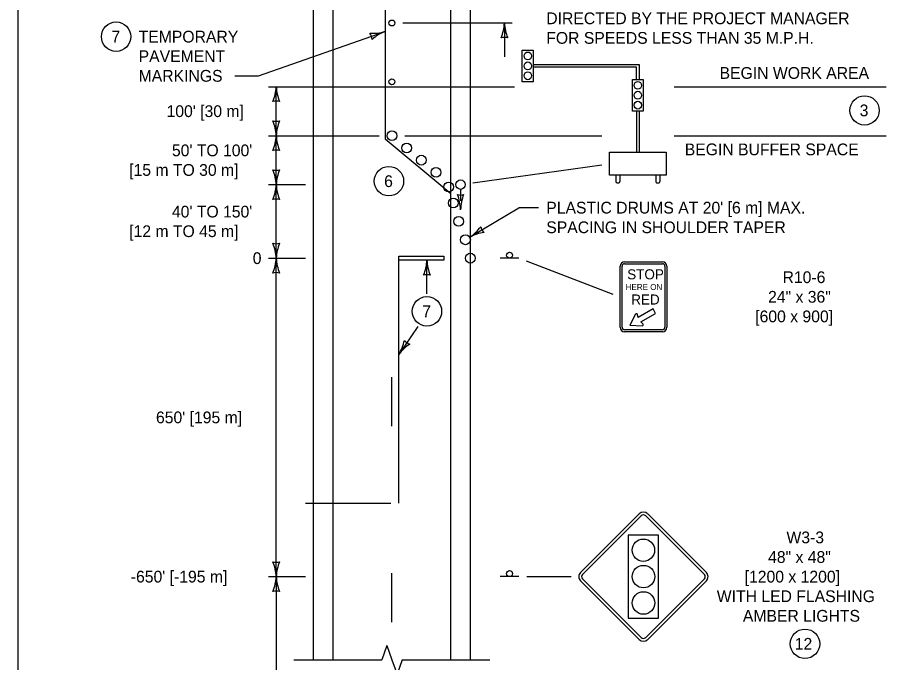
# Model space of a CAD drawing. Extents: x 49991.4 to 50021, y 49987.6 to 50011.4.
# Drawn here: x 50000.336 to 50004.847, y 50004.934 to 50008.223 of the extents above; entities that cross this region are included whole.
import ezdxf

# ---------------------------------------------------------------- set-up
doc = ezdxf.new("R2010")
doc.units = 0
for name, color, linetype in [('Level 1', 7, 'Continuous'), ('Level 2', 7, 'Continuous'), ('Level 3', 7, 'Continuous'), ('Level 6', 7, 'Continuous')]:
    doc.layers.add(name, color=color, linetype=linetype)

msp = doc.modelspace()

# ---------------------------------------------------------------- linework, layer by layer
at = {"layer": 'Level 1'}
for p, q in [((50001.8443, 50004.9471), (50001.8443, 50010.921)), ((50001.9443, 50004.9471), (50001.9443, 50010.921)), ((50002.5443, 50004.9471), (50002.5443, 50010.921)), ((50002.6443, 50004.9471), (50002.6443, 50010.921)), ((50002.2093, 50008.9873), (50002.2093, 50007.6045)), ((50002.9651, 50007.984), (50003.5048, 50007.984)), ((50003.5048, 50007.984), (50003.5048, 50007.908)), ((50003.4921, 50007.9701), (50002.9651, 50007.9701)), ((50003.4921, 50007.908), (50003.4921, 50007.9701)), ((50003.4921, 50007.7462), (50003.4921, 50007.5369)), ((50003.5048, 50007.7462), (50003.5048, 50007.5369)), ((50002.2093, 50007.6045), (50002.5443, 50007.3253)), ((50003.3859, 50007.4192), (50003.3859, 50007.3873)), ((50003.4071, 50007.4192), (50003.4071, 50007.3873)), ((50003.5898, 50007.4192), (50003.5898, 50007.3873)), ((50003.611, 50007.4192), (50003.611, 50007.3873)), ((50002.5943, 50007.3469), (50002.5943, 50007.2885)), ((50003.3923, 50007.3803), (50003.4008, 50007.3803)), ((50003.5962, 50007.3803), (50003.6047, 50007.3803)), ((50002.2793, 50005.7459), (50002.2793, 50006.9859)), ((50002.8923, 50006.9959), (50002.7963, 50006.9959)), ((50003.4086, 50006.643), (50003.4086, 50006.9545)), ((50003.4179, 50006.643), (50003.4179, 50006.9545)), ((50003.4309, 50006.9767), (50003.6237, 50006.9767)), ((50003.4309, 50006.9675), (50003.6237, 50006.9675)), ((50003.6367, 50006.9545), (50003.6367, 50006.643)), ((50003.646, 50006.9545), (50003.646, 50006.643)), ((50003.5761, 50006.7367), (50003.5001, 50006.6928)), ((50003.5891, 50006.7142), (50003.5761, 50006.7367)), ((50003.4871, 50006.7097), (50003.4574, 50006.6532)), ((50003.5001, 50006.6928), (50003.4967, 50006.7084)), ((50003.5131, 50006.6704), (50003.5891, 50006.7142)), ((50003.5249, 50006.6596), (50003.5131, 50006.6704)), ((50003.6237, 50006.63), (50003.4309, 50006.63)), ((50003.4574, 50006.6532), (50003.5212, 50006.6507)), ((50003.4086, 50006.6207), (50003.4086, 50006.6207)), ((50003.6237, 50006.6207), (50003.4309, 50006.6207)), ((50002.2443, 50006.1388), (50002.2443, 50006.3888)), ((50003.5058, 50005.6916), (50003.2064, 50005.3922)), ((50003.5058, 50005.6916), (50003.2064, 50005.3922)), ((50003.5159, 50005.6815), (50003.2165, 50005.3821)), ((50003.5159, 50005.6815), (50003.2165, 50005.3821)), ((50003.5159, 50005.6815), (50003.5159, 50005.6815)), ((50003.5159, 50005.6815), (50003.5159, 50005.6815)), ((50003.8379, 50005.3821), (50003.5385, 50005.6815)), ((50003.8379, 50005.3821), (50003.5385, 50005.6815)), ((50003.848, 50005.3922), (50003.5486, 50005.6916)), ((50003.848, 50005.3922), (50003.5486, 50005.6916)), ((50002.2443, 50005.1388), (50002.2443, 50005.3888)), ((50002.8923, 50005.3709), (50002.7963, 50005.3709)), ((50003.2064, 50005.3495), (50003.5058, 50005.0501)), ((50003.2064, 50005.3495), (50003.5058, 50005.0501)), ((50003.2165, 50005.3596), (50003.5159, 50005.0602)), ((50003.2165, 50005.3596), (50003.5159, 50005.0602)), ((50003.5385, 50005.0602), (50003.8379, 50005.3596)), ((50003.5385, 50005.0602), (50003.8379, 50005.3596)), ((50003.5486, 50005.0501), (50003.848, 50005.3495)), ((50003.5486, 50005.0501), (50003.848, 50005.3495)), ((50003.5272, 50005.0287), (50003.5272, 50005.0287)), ((50003.5272, 50005.0287), (50003.5272, 50005.0287))]:
    msp.add_line(p, q, dxfattribs=at)
for points in [[(50008.6146, 50011.2628), (50000.3356, 50011.2628), (50000.3356, 50000.0624), (50008.6146, 50000.0624)], [(50002.9093, 50008.0579), (50002.9651, 50008.0579), (50002.9651, 50007.8961), (50002.9093, 50007.8961)], [(50003.4704, 50007.908), (50003.5261, 50007.908), (50003.5261, 50007.7462), (50003.4704, 50007.7462)], [(50003.354, 50007.5369), (50003.6429, 50007.5369), (50003.6429, 50007.4192), (50003.354, 50007.4192)], [(50002.2793, 50007.0059), (50002.5093, 50007.0059), (50002.5093, 50006.9859), (50002.2793, 50006.9859)], [(50003.6045, 50005.1592), (50003.6045, 50005.5825), (50003.4499, 50005.5825), (50003.4499, 50005.1592)], [(50003.6045, 50005.1592), (50003.6045, 50005.5825), (50003.4499, 50005.5825), (50003.4499, 50005.1592)]]:
    msp.add_lwpolyline(points, close=True, dxfattribs=at)
msp.add_lwpolyline([(50003.6045, 50005.1593), (50003.6043, 50005.1592)], dxfattribs=at)
msp.add_lwpolyline([(50003.6045, 50005.1593), (50003.6043, 50005.1592)], dxfattribs=at)
for centre, radius in [((50002.2443, 50008.1958), 0.015), ((50002.2443, 50007.8958), 0.015), ((50002.2443, 50007.6209), 0.025), ((50002.3193, 50007.5584), 0.025), ((50002.3943, 50007.4959), 0.025), ((50002.4693, 50007.4334), 0.025), ((50002.5943, 50007.3709), 0.024), ((50002.5337, 50007.3594), 0.025), ((50002.5576, 50007.2771), 0.025), ((50002.5844, 50007.1834), 0.025), ((50002.6193, 50007.0896), 0.025), ((50002.6443, 50006.9959), 0.025), ((50002.8443, 50007.0111), 0.0152), ((50003.5266, 50005.5055), 0.0572), ((50003.5266, 50005.5055), 0.0572), ((50003.5269, 50005.3709), 0.0575), ((50003.5269, 50005.3709), 0.0575), ((50002.8443, 50005.3861), 0.0152), ((50003.5269, 50005.2364), 0.0575), ((50003.5269, 50005.2364), 0.0575)]:
    msp.add_circle(centre, radius, dxfattribs=at)
for centre, radius, start, end in [((50003.4309, 50006.9545), 0.0223, 90, 180), ((50003.4309, 50006.9545), 0.013, 90, 180), ((50003.6237, 50006.9545), 0.0223, 360, 90), ((50003.6237, 50006.9545), 0.013, 360, 90), ((50003.4917, 50006.7073), 0.00514, 12.3804, 152.2438), ((50003.4309, 50006.643), 0.0223, 180, 270), ((50003.4309, 50006.643), 0.013, 180, 270), ((50003.5214, 50006.6558), 0.00514, 267.757, 47.6186), ((50003.6237, 50006.643), 0.0223, 270, 360), ((50003.6237, 50006.643), 0.013, 270, 360), ((50003.5272, 50005.6702), 0.0302, 45.0001, 134.9999), ((50003.5272, 50005.6702), 0.0302, 45.0001, 134.9999), ((50003.5272, 50005.6702), 0.016, 45.0001, 134.9999), ((50003.5272, 50005.6702), 0.016, 45.0001, 134.9999), ((50003.2278, 50005.3709), 0.0302, 134.9999, 225.0001), ((50003.2278, 50005.3709), 0.0302, 134.9999, 225.0001), ((50003.2278, 50005.3709), 0.016, 134.9999, 225.0001), ((50003.2278, 50005.3709), 0.016, 134.9999, 225.0001), ((50003.8266, 50005.3709), 0.016, 314.9999, 45.0001), ((50003.8266, 50005.3709), 0.016, 314.9999, 45.0001), ((50003.8266, 50005.3709), 0.0302, 314.9999, 45.0001), ((50003.8266, 50005.3709), 0.0302, 314.9999, 45.0001), ((50003.5272, 50005.0715), 0.0302, 225.0001, 314.9999), ((50003.5272, 50005.0715), 0.0302, 225.0001, 314.9999), ((50003.5272, 50005.0715), 0.016, 225.0001, 314.9999), ((50003.5272, 50005.0715), 0.016, 225.0001, 314.9999)]:
    msp.add_arc(centre, radius, start, end, dxfattribs=at)
for centre in [(50002.9372, 50008.0276), (50002.9372, 50007.977), (50002.9372, 50007.9265), (50003.4982, 50007.8777), (50003.4982, 50007.8271), (50003.4982, 50007.7765)]:
    msp.add_ellipse(centre, major_axis=(0, 0.0202), ratio=0.91873, dxfattribs=at)
for centre, major_axis, ratio, start_param, end_param in [((50003.3923, 50007.3873), (0, -0.00694), 0.91873, 4.712389, 6.283185), ((50003.4008, 50007.3873), (0, 0.00694), 0.91873, 3.141779, 4.712402), ((50003.5962, 50007.3873), (0, 0.00693), 0.91873, 1.570718, 3.142197), ((50003.6047, 50007.3873), (0, 0.00693), 0.91873, 3.14129, 4.712467), ((50002.5943, 50007.3738), (0, -0.0558), 0.908162, 5.971449, 6.594922), ((50002.3792, 50007.2316), (0, 0.2372), 0.908162, 4.761735, 5.097708), ((50002.7997, 50007.234), (0, -0.2263), 0.908162, 4.318922, 4.671191)]:
    msp.add_ellipse(centre, major_axis=major_axis, ratio=ratio, start_param=start_param, end_param=end_param, dxfattribs=at)
at = {"layer": 'Level 2'}
for centre in [(50000.8375, 50008.1262), (50004.6549, 50007.7497), (50002.229, 50007.3887), (50002.4229, 50006.7247), (50004.3509, 50005.0281)]:
    msp.add_circle(centre, 0.075, dxfattribs=at)
at = {"layer": 'Level 3'}
for p, q in [((50002.2993, 50008.1958), (50002.8578, 50008.1958)), ((50002.8178, 50008.1958), (50002.8178, 50008.0224)), ((50001.6143, 50007.8709), (50001.8043, 50007.8709)), ((50001.6543, 50007.6209), (50001.6543, 50007.8709)), ((50001.8043, 50007.8709), (50002.8693, 50007.8709)), ((50003.6829, 50007.8709), (50004.7645, 50007.8709)), ((50001.6143, 50007.6209), (50002.1793, 50007.6209)), ((50001.6543, 50007.3709), (50001.6543, 50007.6209)), ((50002.3093, 50007.6209), (50003.314, 50007.6209)), ((50003.6829, 50007.6209), (50004.7645, 50007.6209)), ((50002.6577, 50007.3798), (50003.3144, 50007.4724)), ((50001.6143, 50007.3709), (50001.8043, 50007.3709)), ((50001.6543, 50006.9959), (50001.6543, 50007.3709)), ((50002.6407, 50007.1025), (50002.8919, 50007.2535)), ((50002.9914, 50007.2535), (50002.8919, 50007.2535)), ((50001.6143, 50006.9959), (50001.8043, 50006.9959)), ((50001.6543, 50005.7459), (50001.6543, 50006.9959)), ((50002.4229, 50006.8147), (50002.4229, 50006.9881)), ((50002.9297, 50006.9816), (50003.3713, 50006.813)), ((50002.3763, 50006.6477), (50002.2791, 50006.5041)), ((50001.6543, 50005.3709), (50001.6543, 50005.7459)), ((50001.8043, 50005.7459), (50002.2393, 50005.7459)), ((50001.6143, 50005.3709), (50001.8043, 50005.3709)), ((50001.6543, 50005.3709), (50001.6544, 50004.8435)), ((50002.9323, 50005.3709), (50003.1576, 50005.3709))]:
    msp.add_line(p, q, dxfattribs=at)
msp.add_lwpolyline([(50001.4427, 50007.9262), (50001.5644, 50007.9262), (50002.2093, 50008.1528)], dxfattribs=at)
for centre, radius, start, end in [((50002.5957, 50008.2049), 0.2223, 337.456, 357.6395), ((50003.0505, 50008.2073), 0.233, 182.8273, 202.0772), ((50002.1443, 50008.3654), 0.2223, 266.8124, 286.9959), ((50002.0883, 50008.1103), 0.0548, 1.4952, 37.2175), ((50002.2973, 50007.937), 0.233, 112.1837, 131.4335), ((50002.8178, 50008.0676), 0.0548, 72.1388, 107.8612), ((50001.4322, 50007.88), 0.2223, 337.456, 357.6395), ((50001.887, 50007.8823), 0.233, 182.8273, 202.0772), ((50001.6543, 50007.7426), 0.0548, 72.1388, 107.8612), ((50001.6543, 50007.7491), 0.0548, 252.1388, 287.8612), ((50001.4216, 50007.6094), 0.233, 2.8273, 22.0772), ((50001.8764, 50007.6117), 0.2223, 157.456, 177.6395), ((50001.4322, 50007.63), 0.2223, 337.456, 357.6395), ((50001.887, 50007.6323), 0.233, 182.8273, 202.0772), ((50001.6543, 50007.4926), 0.0548, 72.1388, 107.8612), ((50001.6543, 50007.4991), 0.0548, 252.1388, 287.8612), ((50001.4216, 50007.3594), 0.233, 2.8273, 22.0772), ((50001.8764, 50007.3617), 0.2223, 157.456, 177.6395), ((50001.4322, 50007.38), 0.2223, 337.456, 357.6395), ((50001.887, 50007.3823), 0.233, 182.8273, 202.0772), ((50001.6543, 50007.2426), 0.0548, 72.1388, 107.8612), ((50002.511, 50007.296), 0.233, 303.8392, 323.0891), ((50002.7473, 50006.9074), 0.2223, 98.4679, 118.6514), ((50002.7506, 50007.1685), 0.0548, 193.1507, 228.8731), ((50001.6543, 50007.1241), 0.0548, 252.1388, 287.8612), ((50001.4216, 50006.9844), 0.233, 2.8273, 22.0772), ((50001.8764, 50006.9867), 0.2223, 157.456, 177.6395), ((50001.4322, 50007.005), 0.2223, 337.456, 357.6395), ((50001.887, 50007.0073), 0.233, 182.8273, 202.0772), ((50001.6543, 50006.8676), 0.0548, 72.1388, 107.8612), ((50002.0799, 50006.625), 0.233, 328.7394, 347.9892), ((50002.4579, 50006.372), 0.2223, 123.3681, 143.5516), ((50002.351, 50006.6102), 0.0548, 218.0509, 253.7732), ((50001.6543, 50005.4991), 0.0548, 252.1388, 287.8612), ((50001.4216, 50005.3594), 0.233, 2.8273, 22.0772), ((50001.8764, 50005.3617), 0.2223, 157.456, 177.6395), ((50001.4322, 50005.38), 0.2223, 337.456, 357.6395), ((50001.887, 50005.3823), 0.233, 182.8273, 202.0772), ((50001.6543, 50005.2426), 0.0548, 72.1388, 107.8612)]:
    msp.add_arc(centre, radius, start, end, dxfattribs=at)
for centre, major_axis, start_param, end_param in [((50002.2008, 50006.9953), (0, -0.226), 1.177329, 1.529598), ((50002.6557, 50006.9976), (0, -0.2369), 4.761735, 5.097708), ((50002.4229, 50006.8556), (0, 0.0557), 5.971449, 6.594922)]:
    msp.add_ellipse(centre, major_axis=major_axis, ratio=0.983712, start_param=start_param, end_param=end_param, dxfattribs=at)
at = {"layer": 'Level 6'}
for p, q in [((50002.2184, 50005.0202), (50002.1925, 50004.9471)), ((50002.2184, 50005.0202), (50002.2443, 50004.9471)), ((50001.7443, 50004.9471), (50002.1925, 50004.9471)), ((50002.2443, 50004.9471), (50002.2702, 50004.874)), ((50002.2961, 50004.9471), (50002.2702, 50004.874)), ((50002.2961, 50004.9471), (50002.7443, 50004.9471))]:
    msp.add_line(p, q, dxfattribs=at)

# ---------------------------------------------------------------- texts
at = {"layer": 'Level 1'}
for s, height, p in [('STOP', 0.0514, (50003.4442, 50006.8877)), ('HERE ON', 0.03063, (50003.4363, 50006.8333)), ('RED', 0.0514, (50003.4648, 50006.7591))]:
    msp.add_text(s, height=height, rotation=360, dxfattribs=at).set_placement(p)
at = {"layer": 'Level 2'}
for s, p in [('DIRECTED BY THE PROJECT MANAGER ', (50003.0314, 50008.1897)), ('7', (50000.8137, 50008.0962)), ('TEMPORARY', (50000.9525, 50008.0962)), ('FOR SPEEDS LESS THAN 35 M.P.H.', (50003.0314, 50008.0897)), ('PAVEMENT', (50000.9525, 50007.9962)), ('MARKINGS', (50000.9525, 50007.8962)), ('BEGIN WORK AREA', (50003.9153, 50007.9109)), ("100' [30 m]", (50001.0948, 50007.7159)), ('3', (50004.6297, 50007.7197)), ("50' TO 100'", (50001.1223, 50007.5159)), ('BEGIN BUFFER SPACE', (50003.7377, 50007.5209)), ('[15 m TO 30 m]', (50000.9043, 50007.4159)), ('6', (50002.2045, 50007.3587)), ("40' TO 150'", (50001.1223, 50007.2034)), ("PLASTIC DRUMS AT 20' [6 m] MAX.", (50003.0314, 50007.2235)), ('[12 m TO 45 m]', (50000.9043, 50007.1034)), ('SPACING IN SHOULDER TAPER', (50003.0314, 50007.1235)), ('0', (50001.5344, 50006.9659)), ('R10-6', (50004.2365, 50006.8687)), ('24" x 36"', (50004.1627, 50006.7687)), ('7', (50002.3991, 50006.6947)), ('[600 x 900]', (50004.0971, 50006.6687)), ("650' [195 m]", (50001.0409, 50006.1534)), ('W3-3', (50004.2564, 50005.5409)), ('48" x 48"', (50004.1627, 50005.4409)), ("-650' [-195 m]", (50000.9124, 50005.3409)), ('[1200 x 1200]', (50004.0432, 50005.3409)), ('WITH LED FLASHING ', (50003.901, 50005.2409)), ('AMBER LIGHTS', (50004.0342, 50005.1409)), ('12', (50004.2988, 50004.9981))]:
    msp.add_text(s, height=0.06, dxfattribs=at).set_placement(p)

doc.saveas('drawing.dxf')
